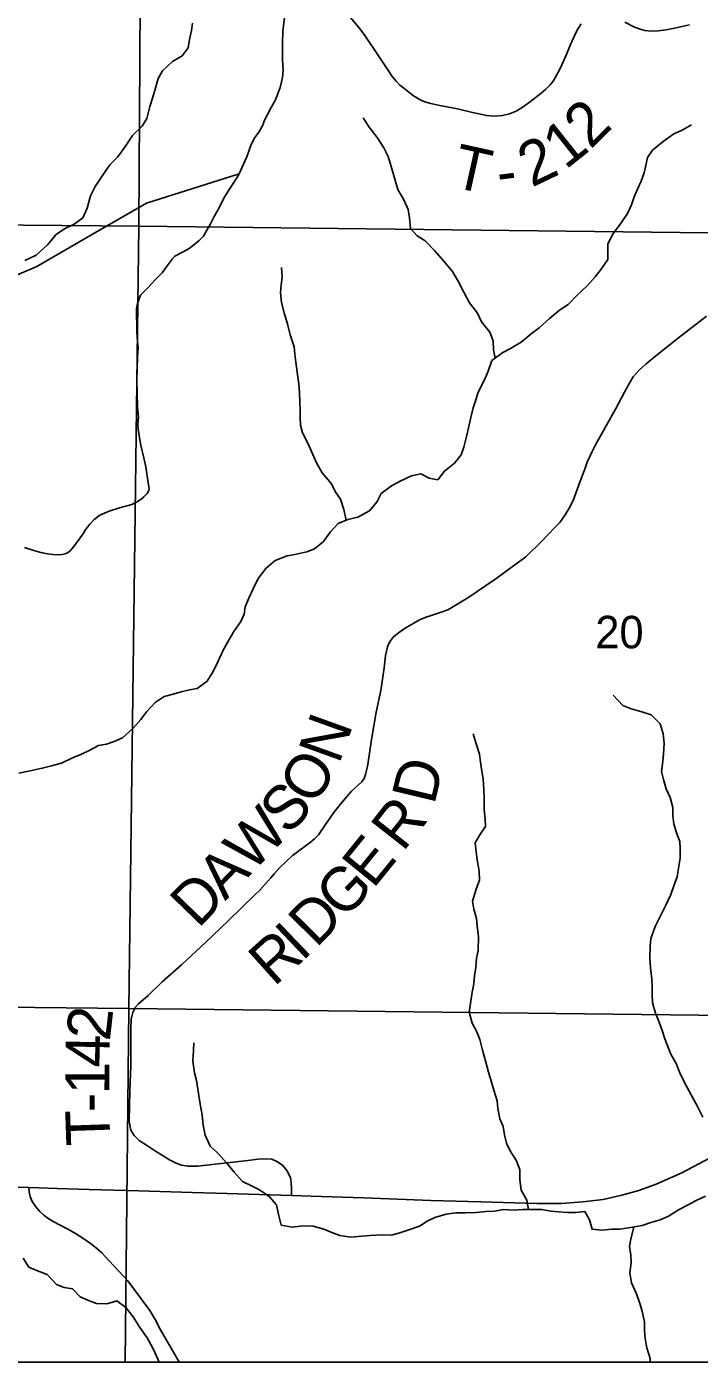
# Model space of a CAD drawing. Extents: x 0 to 191, y 0 to 55.
# Drawn here: x 143.865 to 144.298, y 18.618 to 19.478 of the extents above; entities that cross this region are included whole.
import ezdxf

# ---------------------------------------------------------------- set-up
doc = ezdxf.new("R2010")
doc.units = 0
for name, color, linetype in [('GM_X_Corporation', 7, 'Continuous'), ('GM_X_County_Road', 7, 'Continuous'), ('GM_X_Minor_River', 7, 'Continuous'), ('GM_X_Section_Text', 7, 'Continuous'), ('GM_X_State_Route', 7, 'Continuous'), ('GM_X_Township_Road', 7, 'Continuous'), ('GM_X_Township_Road_Text', 7, 'Continuous')]:
    doc.layers.add(name, color=color, linetype=linetype)

msp = doc.modelspace()

# ---------------------------------------------------------------- linework, layer by layer
at = {"layer": 'GM_X_Corporation'}
for points in [[(143.27549, 22.87347), (143.27549, 18.61761), (147.4432, 18.61761)], [(143.27549, 20.86338), (143.27549, 18.61761), (144.95109, 18.61761), (144.95114, 18.62602), (144.95248, 18.83447), (144.96379, 19.38085), (144.96901, 19.63307), (144.9877, 20.24306), (144.98772, 20.24394), (144.99193, 20.41256)]]:
    msp.add_lwpolyline(points, dxfattribs=at)
for points in [[(143.93984, 19.85386), (143.93686, 19.34982), (143.41575, 19.35448), (143.42494, 19.86182)], [(143.93984, 19.85386), (144.45738, 19.84668), (144.45116, 19.34394), (143.93686, 19.34982)], [(143.41575, 19.35448), (143.93686, 19.34982), (143.93048, 18.84555), (143.40538, 18.85112)], [(144.45116, 19.34394), (144.44459, 18.83967), (143.93048, 18.84555), (143.93686, 19.34982)], [(143.40227, 18.61761), (143.92816, 18.61761), (143.93048, 18.84555), (143.40538, 18.85112)], [(143.92816, 18.61761), (144.44151, 18.61761), (144.44459, 18.83967), (143.93048, 18.84555)]]:
    msp.add_lwpolyline(points, close=True, dxfattribs=at)
at = {"layer": 'GM_X_County_Road'}
msp.add_lwpolyline([(143.96316, 18.61761), (143.9619, 18.61965), (143.95761, 18.62663), (143.95084, 18.63858), (143.94733, 18.64514), (143.94393, 18.65099), (143.93843, 18.65843), (143.92982, 18.67006), (143.91773, 18.68307), (143.91305, 18.68817), (143.90983, 18.69105), (143.90642, 18.69378), (143.90086, 18.69771), (143.89607, 18.70069), (143.891, 18.70338), (143.88171, 18.70838), (143.87817, 18.71058), (143.87569, 18.71235), (143.8731, 18.71469), (143.87051, 18.71774), (143.86817, 18.72121), (143.86686, 18.72444), (143.86615, 18.72756), (143.86604, 18.73029)], dxfattribs=at)
at = {"layer": 'GM_X_Minor_River'}
for points in [[(143.86345, 19.32785), (143.87061, 19.33115), (143.87793, 19.33786), (143.88354, 19.34456), (143.88899, 19.34822), (143.89521, 19.35113), (143.90066, 19.35535), (143.90362, 19.36145), (143.90562, 19.36944), (143.90878, 19.37554), (143.91344, 19.38261), (143.9181, 19.38948), (143.92335, 19.39466), (143.9282, 19.40135), (143.93286, 19.40822), (143.93905, 19.41435), (143.94203, 19.41932), (143.94403, 19.42692), (143.94586, 19.43301), (143.94732, 19.43815), (143.94933, 19.445), (143.95212, 19.44996), (143.9585, 19.45609), (143.96471, 19.45976), (143.96863, 19.46492), (143.96952, 19.47024), (143.97079, 19.47594), (143.9715, 19.48069)], [(144.16653, 19.26479), (144.16546, 19.27008), (144.1654, 19.27596), (144.16326, 19.28163), (144.1577, 19.28821), (144.15518, 19.29387), (144.15, 19.30045), (144.14633, 19.30724), (144.14285, 19.31404), (144.139, 19.32063), (144.13325, 19.32759), (144.1275, 19.33417), (144.12138, 19.34037), (144.11623, 19.34354), (144.11202, 19.34843), (144.11138, 19.35525), (144.11057, 19.36055), (144.10766, 19.36678), (144.10381, 19.37357), (144.09949, 19.38831), (144.09772, 19.39475), (144.09482, 19.4004), (144.09059, 19.407), (144.08541, 19.41358), (144.08156, 19.41961)], [(144.25184, 19.35802), (144.25443, 19.36354), (144.25627, 19.36868), (144.2583, 19.37382), (144.26071, 19.37897), (144.26274, 19.3843), (144.26382, 19.38905), (144.26472, 19.39418), (144.26808, 19.39896), (144.27483, 19.40453), (144.28179, 19.40934), (144.28707, 19.41167), (144.29309, 19.41515)], [(143.85947, 18.99726), (143.86683, 18.99886), (143.87458, 19.00045), (143.88062, 19.00203), (143.88704, 19.00381), (143.8942, 19.00729), (143.89986, 19.00963), (143.90476, 19.01195), (143.91078, 19.01505), (143.91607, 19.01605), (143.92098, 19.01762), (143.92644, 19.02014), (143.9332, 19.02628), (143.93825, 19.03183), (143.9418, 19.0368), (143.94741, 19.04292), (143.95324, 19.04677), (143.9591, 19.04816), (143.96419, 19.04973), (143.96948, 19.05092), (143.9744, 19.05192), (143.98098, 19.05654), (143.9847, 19.06284), (143.98785, 19.06913), (143.99118, 19.07656), (143.99509, 19.08342), (143.99806, 19.08858), (144.00254, 19.09507), (144.00476, 19.09983), (144.00547, 19.10458), (144.00788, 19.11011), (144.01066, 19.1162), (144.01381, 19.12268), (144.01866, 19.12918), (144.02467, 19.13436), (144.0324, 19.13748), (144.0375, 19.13829), (144.04525, 19.14007), (144.05015, 19.14183), (144.05597, 19.14663), (144.06045, 19.15294), (144.06532, 19.1583), (144.07154, 19.16083), (144.07815, 19.16241), (144.08549, 19.16647), (144.09054, 19.1724), (144.09314, 19.17755), (144.09972, 19.18255), (144.10574, 19.18583), (144.11271, 19.18894), (144.11876, 19.19014), (144.12409, 19.18754), (144.12959, 19.18646), (144.13389, 19.192), (144.14046, 19.19719), (144.14457, 19.20254), (144.14641, 19.20749), (144.14823, 19.21509), (144.1495, 19.21985), (144.15095, 19.2265), (144.1524, 19.23277), (144.15405, 19.23791), (144.15571, 19.24286), (144.15997, 19.25125), (144.162, 19.25639), (144.16439, 19.26324), (144.17153, 19.26844), (144.17643, 19.27095), (144.1834, 19.27501), (144.18978, 19.28038), (144.19504, 19.28442), (144.2016, 19.29036), (144.20798, 19.29574), (144.21363, 19.2994), (144.21944, 19.30534), (144.22619, 19.31167), (144.23105, 19.31722), (144.23498, 19.32219), (144.23927, 19.32849), (144.23916, 19.33835), (144.24232, 19.34445), (144.24773, 19.3521), (144.25184, 19.35802)], [(144.07059, 19.16044), (144.06901, 19.16725), (144.06686, 19.17386), (144.0634, 19.17895), (144.06108, 19.18385), (144.05514, 19.19081), (144.05147, 19.19741), (144.04818, 19.20458), (144.04605, 19.20949), (144.04238, 19.21666), (144.04119, 19.22158), (144.04095, 19.22651), (144.0409, 19.23125), (144.04066, 19.23637), (144.0404, 19.24262), (144.03997, 19.24812), (144.03915, 19.25437), (144.03812, 19.26213), (144.0375, 19.26744), (144.03707, 19.27217), (144.03453, 19.27992), (144.03275, 19.28692), (144.0306, 19.29411), (144.02883, 19.30072), (144.02819, 19.30698), (144.02871, 19.3121), (144.02923, 19.31704), (144.02878, 19.32329)], [(144.30042, 18.77558), (144.29714, 18.78238), (144.29443, 18.78728), (144.29154, 18.79275), (144.28864, 18.79784), (144.28574, 18.80425), (144.28322, 18.81011), (144.27975, 18.81614), (144.27799, 18.82105), (144.27605, 18.82615), (144.27429, 18.83144), (144.27234, 18.83673), (144.27001, 18.84258), (144.26805, 18.84939), (144.2678, 18.8547), (144.26775, 18.85944), (144.26751, 18.86456), (144.26668, 18.87194), (144.26624, 18.87801), (144.26654, 18.88578), (144.26705, 18.89072), (144.26981, 18.89852), (144.27352, 18.90614), (144.27668, 18.91224), (144.27983, 18.9191), (144.28185, 18.92462), (144.28387, 18.93052), (144.28494, 18.93736), (144.28583, 18.94249), (144.28596, 18.94837), (144.28572, 18.9533), (144.28358, 18.95877), (144.28182, 18.96463), (144.2812, 18.96975), (144.28114, 18.97524), (144.27937, 18.98167), (144.27685, 18.98715), (144.27509, 18.9932), (144.2739, 18.99831), (144.27459, 19.00514), (144.27511, 19.00988), (144.27561, 19.01653), (144.27498, 19.02259), (144.27302, 19.02902), (144.26709, 19.03483), (144.26044, 19.03704), (144.25436, 19.03887), (144.24885, 19.0409), (144.24272, 19.04767)], [(144.18819, 18.71602), (144.18699, 18.72208), (144.18333, 18.72849), (144.18251, 18.73512), (144.18244, 18.74175), (144.1803, 18.74742), (144.17625, 18.75382), (144.17393, 18.75892), (144.17255, 18.76422), (144.17174, 18.76952), (144.1696, 18.77461), (144.16821, 18.78124), (144.16778, 18.78616), (144.16563, 18.79297), (144.16386, 18.79958), (144.16229, 18.8045), (144.16052, 18.81112), (144.15836, 18.81868), (144.15677, 18.82568), (144.15464, 18.83097), (144.15174, 18.83625), (144.14978, 18.84324), (144.15084, 18.85027), (144.15173, 18.85616), (144.15281, 18.86148), (144.15332, 18.86698), (144.15403, 18.87192), (144.15453, 18.87818), (144.15562, 18.88293), (144.1559, 18.89204), (144.15508, 18.89867), (144.15446, 18.90359), (144.15288, 18.90964), (144.15188, 18.91475), (144.15445, 18.92255), (144.15648, 18.92845), (144.15623, 18.93414), (144.15501, 18.94152), (144.1544, 18.94663), (144.15377, 18.95251), (144.15674, 18.95747), (144.16029, 18.963), (144.16024, 18.96774), (144.15961, 18.97362), (144.15953, 18.9812), (144.15929, 18.98651), (144.15883, 18.99371), (144.15803, 18.99863), (144.15721, 19.0045), (144.1564, 19.00961), (144.15444, 19.01623), (144.15248, 19.02266)], [(144.30227, 18.72478), (144.29624, 18.72188), (144.29097, 18.71917), (144.28513, 18.71608), (144.27836, 18.71183), (144.27289, 18.7095), (144.26685, 18.70773), (144.26138, 18.70578), (144.25382, 18.70438), (144.24701, 18.70336), (144.2419, 18.70349), (144.23547, 18.70267), (144.22903, 18.70336), (144.22745, 18.70941), (144.22437, 18.71469), (144.21869, 18.71425), (144.2132, 18.7142), (144.20752, 18.71452), (144.2024, 18.71503), (144.19652, 18.71611), (144.18441, 18.71599), (144.17892, 18.71574), (144.17172, 18.71604), (144.16643, 18.71504), (144.16075, 18.71479), (144.15432, 18.71416), (144.14732, 18.7139), (144.14126, 18.71402), (144.13502, 18.71301), (144.12766, 18.71085), (144.12276, 18.70852), (144.11787, 18.70544), (144.11164, 18.70329), (144.10523, 18.70114), (144.09975, 18.69956), (144.09369, 18.69969), (144.08575, 18.69923), (144.08064, 18.69899), (144.07364, 18.69835), (144.06643, 18.69941), (144.0613, 18.70125), (144.05617, 18.70347), (144.04933, 18.7053), (144.04289, 18.70561), (144.03571, 18.70478), (144.02869, 18.70604), (144.02711, 18.7119), (144.02552, 18.71909), (144.02092, 18.72454), (144.01463, 18.72883), (144.00988, 18.73106), (144.0036, 18.73422), (143.99842, 18.74024), (143.99363, 18.74587), (143.98769, 18.75264), (143.98292, 18.75695), (143.97962, 18.76393), (143.97842, 18.77037), (143.97778, 18.77719), (143.97639, 18.784), (143.97396, 18.79915), (143.97277, 18.80425), (143.97175, 18.81164), (143.97206, 18.81866), (143.97239, 18.82359)], [(144.25604, 18.70479), (144.25426, 18.69812), (144.25319, 18.69242), (144.254, 18.68674), (144.25424, 18.68163), (144.25336, 18.67536), (144.25456, 18.66892), (144.25767, 18.66175), (144.25981, 18.65552), (144.26138, 18.6506), (144.26278, 18.64341), (144.26283, 18.63791), (144.26326, 18.63299), (144.26427, 18.62693), (144.26643, 18.61994), (144.2666, 18.61761)], [(143.8623, 18.6848), (143.86595, 18.67895), (143.87147, 18.67655), (143.87774, 18.67414), (143.88368, 18.66776), (143.88881, 18.66572), (143.89412, 18.66502), (143.89909, 18.65976), (143.90442, 18.65735), (143.90955, 18.65551), (143.91618, 18.6552), (143.9226, 18.65716), (143.92851, 18.65286), (143.9333, 18.64684), (143.93754, 18.64006), (143.94215, 18.63328), (143.9462, 18.62631), (143.94911, 18.61951), (143.95005, 18.61761)]]:
    msp.add_lwpolyline(points, dxfattribs=at)
at = {"layer": 'GM_X_State_Route'}
msp.add_lwpolyline([(143.85573, 18.73057), (143.86604, 18.73029), (143.87242, 18.73004), (143.88412, 18.72972), (143.90476, 18.72908), (143.93695, 18.72802), (143.97123, 18.72696), (143.99374, 18.72632), (144.0353, 18.72505), (144.04771, 18.72464), (144.08188, 18.72359), (144.12517, 18.72198), (144.15731, 18.72109), (144.19349, 18.71996), (144.20916, 18.71996), (144.22314, 18.72093), (144.23622, 18.72262), (144.24833, 18.72529), (144.25916, 18.72836), (144.2703, 18.73231), (144.28686, 18.73966), (144.30519, 18.74944)], dxfattribs=at)
at = {"layer": 'GM_X_Township_Road'}
for points in [[(143.94153, 19.17692), (143.94226, 19.17766), (143.94328, 19.17941), (143.94351, 19.18088), (143.94288, 19.18455), (143.94136, 19.19474), (143.94015, 19.20064), (143.93819, 19.20869), (143.93729, 19.21352), (143.93644, 19.21906), (143.93613, 19.22228), (143.93662, 19.22698), (143.93609, 19.23346), (143.93559, 19.25072), (143.93609, 19.26538), (143.93644, 19.27164), (143.93609, 19.27535), (143.93568, 19.28179), (143.93542, 19.2969), (143.936, 19.30007), (143.93801, 19.3053), (143.94235, 19.31), (143.94753, 19.31541), (143.95187, 19.31983), (143.95522, 19.32435), (143.95831, 19.32864), (143.96018, 19.33048), (143.96537, 19.33334), (143.96921, 19.33548), (143.97552, 19.34036), (143.97847, 19.34353), (143.98075, 19.34724), (143.98316, 19.3514), (143.98553, 19.35609), (143.9888, 19.36217), (143.99184, 19.36834), (143.99676, 19.37603), (144.00006, 19.38095), (144.00156, 19.38365), (144.0065, 19.39459), (144.00936, 19.4025), (144.01169, 19.40693), (144.01419, 19.41041), (144.01678, 19.41506), (144.01777, 19.41775), (144.02228, 19.42628), (144.02492, 19.43125), (144.02805, 19.43921), (144.02894, 19.44292), (144.02948, 19.44578), (144.02988, 19.45056), (144.02953, 19.45727), (144.02939, 19.46809), (144.02975, 19.47529), (144.03123, 19.48807)], [(144.22208, 19.4803), (144.22003, 19.47736), (144.21859, 19.47456), (144.21518, 19.467), (144.21239, 19.46002), (144.20863, 19.45192), (144.20545, 19.44591), (144.20389, 19.44339), (144.20203, 19.44098), (144.19932, 19.43819), (144.19629, 19.43559), (144.18935, 19.43028), (144.18408, 19.42644), (144.18019, 19.42398), (144.1759, 19.42218), (144.1714, 19.42113), (144.16597, 19.42074), (144.1612, 19.42117), (144.15209, 19.42322), (144.14228, 19.42543), (144.13088, 19.42768), (144.12514, 19.429), (144.12188, 19.42982), (144.11921, 19.43086), (144.11645, 19.4323), (144.11389, 19.43396), (144.11087, 19.43625), (144.10773, 19.43889), (144.10521, 19.44079), (144.1028, 19.44323), (144.10021, 19.44637), (144.09784, 19.45006), (144.08974, 19.46219), (144.08473, 19.46948), (144.08214, 19.47348), (144.0788, 19.47798), (144.07306, 19.48465)], [(144.29192, 19.47964), (144.2823, 19.47747), (144.27679, 19.47635), (144.27168, 19.47569), (144.2671, 19.47549), (144.26311, 19.47596), (144.26, 19.47685), (144.25644, 19.47821), (144.25016, 19.48131)], [(143.8211, 19.30256), (143.87121, 19.3238), (143.90747, 19.34494), (143.94185, 19.36474), (144.00156, 19.38365)], [(143.9425, 18.75707), (143.93716, 18.76066), (143.93394, 18.76372), (143.93175, 18.76723), (143.93071, 18.77277), (143.93117, 18.79253), (143.93175, 18.80867), (143.93163, 18.83253), (143.93186, 18.83869), (143.93296, 18.84301), (143.93474, 18.84653), (143.9367, 18.84855), (143.94287, 18.85396), (143.95192, 18.86272), (143.96465, 18.87408), (143.97975, 18.88814), (143.99439, 18.90214), (144.01156, 18.91891), (144.0149, 18.92196), (144.02193, 18.9298), (144.02424, 18.93263), (144.0277, 18.9366), (144.03599, 18.94421), (144.04729, 18.95256), (144.05006, 18.95493), (144.05265, 18.95758), (144.0572, 18.96426), (144.06268, 18.97193), (144.06775, 18.97844), (144.07403, 18.9857), (144.07847, 18.98973), (144.08054, 18.99175), (144.08204, 18.99383), (144.08308, 18.99653), (144.08388, 18.99982), (144.0844, 19.00282), (144.08682, 19.01912), (144.08988, 19.03664), (144.09282, 19.05059), (144.095, 19.0652), (144.09598, 19.07312), (144.09708, 19.07871), (144.09835, 19.08142), (144.0995, 19.08321), (144.10088, 19.08499), (144.10417, 19.08782), (144.10849, 19.0907), (144.11829, 19.09629), (144.12209, 19.0979), (144.13246, 19.10136), (144.13598, 19.10263), (144.13874, 19.10401), (144.14906, 19.11041), (144.16629, 19.1221), (144.18635, 19.1368), (144.19672, 19.14677), (144.20484, 19.15536), (144.20824, 19.15893), (144.21176, 19.16388), (144.21441, 19.16803), (144.21683, 19.17299), (144.22213, 19.18722), (144.22432, 19.19322), (144.22599, 19.19777), (144.22899, 19.20417), (144.23129, 19.20883), (144.23614, 19.21765), (144.24426, 19.23189), (144.24991, 19.24289), (144.25342, 19.24906), (144.25567, 19.25269), (144.25959, 19.25724), (144.26391, 19.26116), (144.27008, 19.26629), (144.28477, 19.27799), (144.30293, 19.29193)], [(143.86326, 19.14279), (143.8692, 19.14091), (143.87358, 19.13962), (143.87577, 19.13903), (143.87805, 19.13872), (143.8815, 19.13827), (143.88534, 19.1381), (143.88744, 19.13832), (143.88928, 19.13872), (143.89089, 19.13939), (143.89232, 19.14033), (143.89397, 19.14216), (143.89688, 19.14592), (143.90112, 19.15204), (143.90233, 19.15392), (143.90519, 19.15781), (143.9081, 19.16085), (143.91172, 19.16362), (143.91776, 19.16622), (143.92442, 19.16823), (143.93233, 19.17055), (143.93528, 19.1719), (143.93846, 19.17395), (143.94007, 19.17543), (143.94153, 19.17692)], [(144.0353, 18.72505), (144.03525, 18.72955), (144.03501, 18.73318), (144.03461, 18.73675), (144.03219, 18.7413), (144.02943, 18.74459), (144.02574, 18.74712), (144.02257, 18.74845), (144.01899, 18.74879), (144.01387, 18.74851), (144.00707, 18.7477), (143.99375, 18.74626), (143.97462, 18.74401), (143.96863, 18.74395), (143.96448, 18.7447), (143.96085, 18.74603), (143.9567, 18.74799), (143.94702, 18.75404), (143.9425, 18.75707)]]:
    msp.add_lwpolyline(points, dxfattribs=at)

# ---------------------------------------------------------------- texts
at = {"layer": 'GM_X_Section_Text'}
msp.add_text('20', height=0.020928, rotation=0.00001, dxfattribs=at).set_placement((144.23116, 19.07779))
at = {"layer": 'GM_X_Township_Road_Text'}
for s, rotation, p in [('2', 44.76557, (144.22811, 19.39901)), ('1', 38.43073, (144.21185, 19.38587)), ('T', 347.48049, (144.13778, 19.37544)), ('2', 25.54752, (144.19016, 19.37464)), ('-', 7.41523, (144.16923, 19.37036)), ('N', 70.15405, (144.06593, 19.00258)), ('O', 58.13235, (144.0499, 18.9755)), ('D', 76.54286, (144.12729, 18.97631)), ('S', 46.87292, (144.03309, 18.95668)), ('W', 45.97626, (144.00988, 18.93266)), ('R', 51.89587, (144.10713, 18.94602)), ('E', 50.90393, (144.08794, 18.92227)), ('A', 45.97625, (143.99251, 18.91468)), ('D', 45.97625, (143.97513, 18.89671)), ('G', 46.24958, (144.06898, 18.90232)), ('D', 45.45016, (144.05114, 18.8842)), ('I', 43.67016, (144.04202, 18.87547)), ('R', 41.96284, (144.02399, 18.85924)), ('2', 83.60614, (143.91811, 18.82411)), ('4', 88.92548, (143.91783, 18.80745)), ('1', 89.87961, (143.9178, 18.79022)), ('-', 90.17074, (143.91783, 18.77869)), ('T', 91.98031, (143.91856, 18.75773))]:
    msp.add_text(s, height=0.02841, rotation=rotation, dxfattribs=at).set_placement(p)

doc.saveas('drawing.dxf')
